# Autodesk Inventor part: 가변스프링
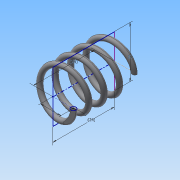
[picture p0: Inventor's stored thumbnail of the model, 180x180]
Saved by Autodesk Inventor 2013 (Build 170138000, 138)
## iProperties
Created: 2015-09
Part Number: 가변스프링
Material: 일반
Document SubType Name: Modeling
Designer: Administrator
Density: 1 g/cm^3
Mass: 0.625251 g
Surface Area: 12.7437 cm^2
Volume: 0.625251 cm^3
Author: Administrator
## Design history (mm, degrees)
sketch "스케치1"
  geometry: L1 (0, 0)-(0, 42); L2 (0, 0)-(8, 0); L3 (0, 42)-(8, 42); C1 r 1 at (8, 0)
  constraints: 6 end point, 2 parallel, 1 centre point, 1 coincident, 1 perpendicular, 1 vertical
  dimensions: "d0" = 42 distance of L1.start L1.end (derived); "d2" = 2 diameter of C1; "d3" = 8 distance of L1.start L2.end
feature "코일1" pitch "d4" = 10; turns "d6" = 4; dims "d5" = 42 (= d0), "d7" = 0, angle "d8" = 90 deg, angle "d9" = 90 deg, "d10" = 0, "d11" = 0
sketch "스케치2"
  geometry: L1 (42, 10)-(0, 10); L2 (0, 10)-(0, -10); L3 (0, -10)-(42, -10); L4 (42, -10)-(42, 10); 2 further points
  constraints: 8 end point, 2 parallel, 1 coincident, 1 horizontal, 1 midpoint, 1 perpendicular
  dimensions: "d12" = 42 distance of L2.end L3.end (derived); "d14" = 20 distance of L3.end L1.start
extrude "돌출1" sketch "스케치2" stored distance "d15" = 10; taper "d16" = 0 deg
node "솔리드1"
